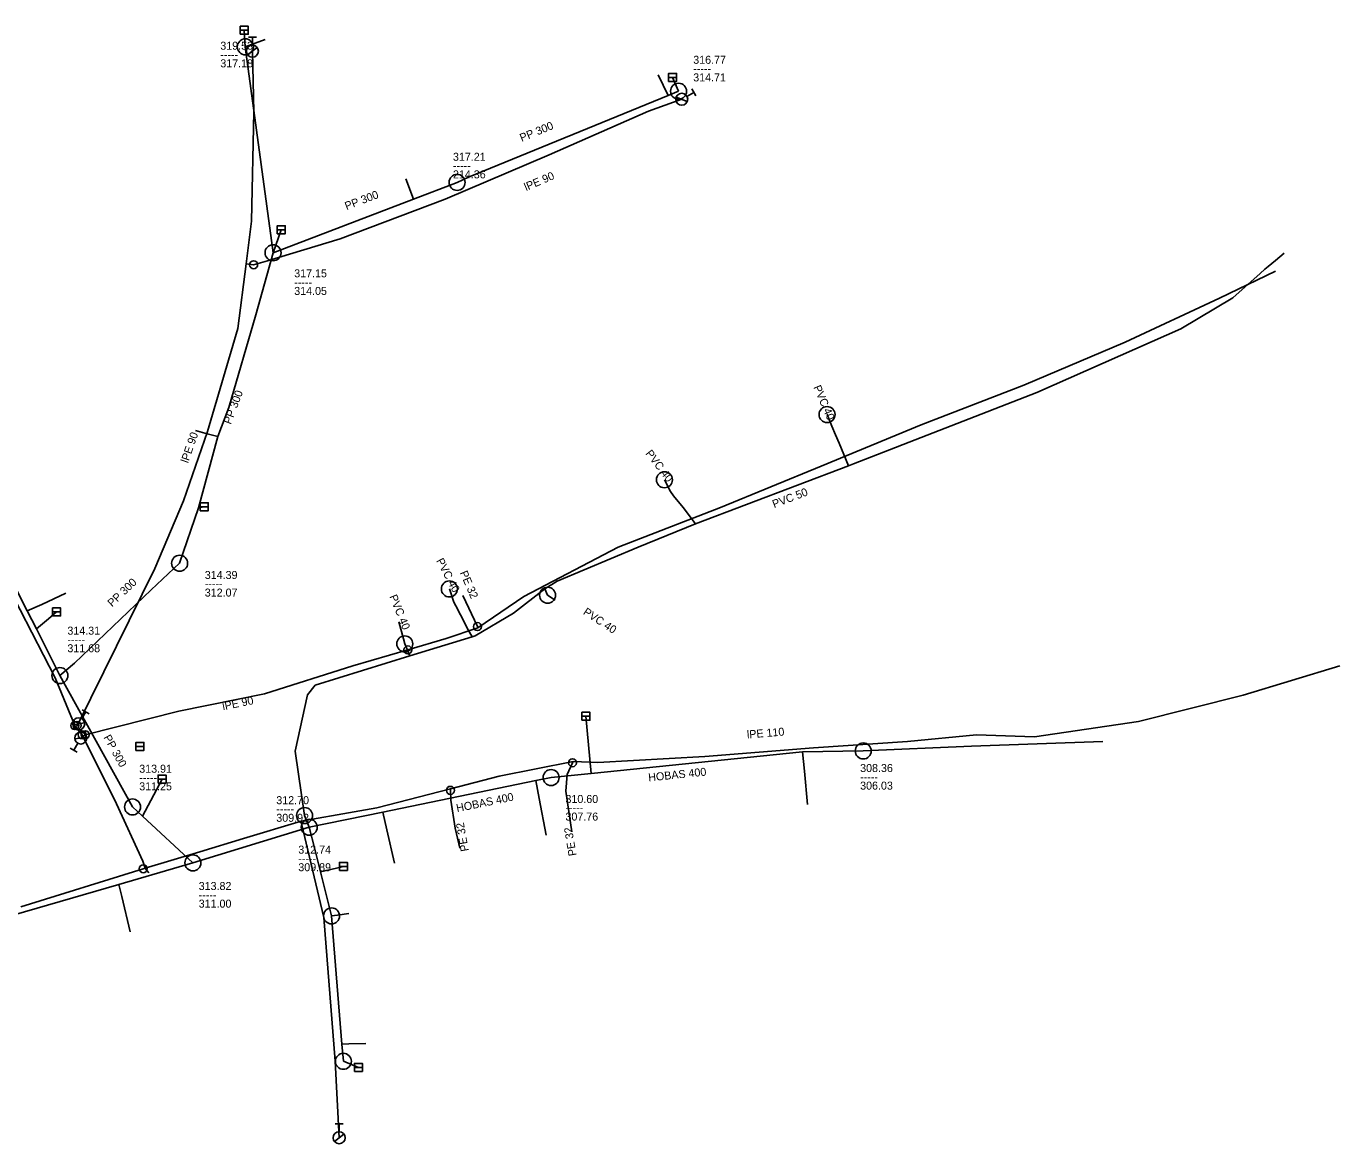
# Model space of a CAD drawing. Extents: x -770550 to -770198, y -1055065 to -1054790.
# Drawn here: x -770362.5 to -770198.4, y -1054983.3 to -1054843.6 of the extents above; entities that cross this region are included whole.
import ezdxf

# ---------------------------------------------------------------- set-up
doc = ezdxf.new("R2010")
doc.units = 0
doc.layers.add('Level 0', color=7, linetype='Continuous')

msp = doc.modelspace()

# ---------------------------------------------------------------- linework, layer by layer
at = {"layer": 'Level 0'}
for p, q in [((-770335.78, -1054844.13), (-770334.78, -1054844.13)), ((-770335.28, -1054844.13), (-770335.15, -1054846.2)), ((-770335.15, -1054846.2), (-770332.67, -1054845.28)), ((-770335.15, -1054846.2), (-770331.74, -1054871.32)), ((-770334.86, -1054847.2), (-770333.68, -1054846.28)), ((-770334.77, -1054844.99), (-770333.77, -1054844.99)), ((-770334.27, -1054845.99), (-770334.27, -1054844.99)), ((-770334.1, -1054854.32), (-770334.27, -1054846.74)), ((-770282.29, -1054852.28), (-770283.55, -1054849.69)), ((-770282.25, -1054850.03), (-770281.25, -1054850.03)), ((-770281.75, -1054850.03), (-770281, -1054851.75)), ((-770279.34, -1054851.45), (-770278.84, -1054852.32)), ((-770282.29, -1054852.28), (-770307.27, -1054862.47)), ((-770284.76, -1054854.22), (-770280.61, -1054852.76)), ((-770281, -1054851.75), (-770282.29, -1054852.28)), ((-770281.3, -1054852.48), (-770279.91, -1054853.04)), ((-770279.96, -1054852.39), (-770279.09, -1054851.89)), ((-770334.4, -1054867.97), (-770334.1, -1054854.32)), ((-770297.19, -1054859.7), (-770284.76, -1054854.22)), ((-770310.16, -1054865.24), (-770297.19, -1054859.7)), ((-770314.13, -1054865.26), (-770315.08, -1054862.68)), ((-770307.27, -1054862.47), (-770308.68, -1054863.14)), ((-770308.68, -1054863.14), (-770314.13, -1054865.26)), ((-770314.13, -1054865.26), (-770331.69, -1054871.94)), ((-770323.3, -1054870.19), (-770310.16, -1054865.24)), ((-770335.06, -1054873.31), (-770334.4, -1054867.97)), ((-770330.66, -1054869.06), (-770331.69, -1054871.94)), ((-770331.16, -1054869.06), (-770330.16, -1054869.06)), ((-770332.37, -1054872.94), (-770323.3, -1054870.19)), ((-770331.69, -1054871.94), (-770333.83, -1054879.69)), ((-770331.74, -1054871.32), (-770331.69, -1054871.94)), ((-770205.3, -1054871.97), (-770206.41, -1054872.9)), ((-770336.07, -1054881.39), (-770335.06, -1054873.31)), ((-770335.06, -1054873.31), (-770334.11, -1054873.43)), ((-770334.11, -1054873.43), (-770332.37, -1054872.94)), ((-770206.41, -1054874.22), (-770213.4, -1054877.62)), ((-770207.72, -1054873.99), (-770208.3, -1054874.51)), ((-770207.33, -1054873.67), (-770207.72, -1054873.99)), ((-770206.41, -1054872.9), (-770207.33, -1054873.67)), ((-770208.3, -1054874.51), (-770211.72, -1054877.57)), ((-770213.4, -1054877.62), (-770225.2, -1054883.12)), ((-770211.72, -1054877.57), (-770218.24, -1054881.44)), ((-770333.83, -1054879.69), (-770337.22, -1054891.29)), ((-770339.86, -1054894.27), (-770336.07, -1054881.39)), ((-770218.24, -1054881.44), (-770221.83, -1054883.03)), ((-770225.2, -1054883.12), (-770237.84, -1054888.47)), ((-770221.83, -1054883.03), (-770236.24, -1054889.42)), ((-770237.84, -1054888.47), (-770250.69, -1054893.44)), ((-770236.24, -1054889.42), (-770259.16, -1054898.34)), ((-770337.22, -1054891.29), (-770338.59, -1054894.92)), ((-770262.45, -1054892.16), (-770261.86, -1054893.62)), ((-770250.69, -1054893.44), (-770263.17, -1054898.6)), ((-770261.86, -1054893.62), (-770261.4, -1054894.69)), ((-770342.87, -1054902.96), (-770339.86, -1054894.27)), ((-770339.9, -1054894.56), (-770341.36, -1054894.17)), ((-770338.59, -1054894.92), (-770341.02, -1054903.82)), ((-770338.59, -1054894.92), (-770339.9, -1054894.56)), ((-770261.4, -1054894.69), (-770260.95, -1054895.74)), ((-770260.95, -1054895.74), (-770259.75, -1054898.56)), ((-770259.75, -1054898.56), (-770278.9, -1054905.84)), ((-770263.17, -1054898.6), (-770275.76, -1054903.79)), ((-770259.16, -1054898.34), (-770259.75, -1054898.56)), ((-770282.03, -1054901.79), (-770282.77, -1054900.31)), ((-770281.64, -1054902.3), (-770282.03, -1054901.79)), ((-770280.43, -1054903.79), (-770281.64, -1054902.3)), ((-770346.45, -1054911.4), (-770342.87, -1054902.96)), ((-770341.02, -1054903.82), (-770343.36, -1054910.75)), ((-770341.02, -1054903.82), (-770340.29, -1054903.68)), ((-770340.79, -1054903.68), (-770339.79, -1054903.68)), ((-770275.76, -1054903.79), (-770288.55, -1054908.73)), ((-770278.9, -1054905.84), (-770280.43, -1054903.79)), ((-770278.9, -1054905.84), (-770286.07, -1054908.72)), ((-770288.55, -1054908.73), (-770300.36, -1054914.91)), ((-770286.07, -1054908.72), (-770296.16, -1054912.97)), ((-770358.93, -1054925.08), (-770366.23, -1054910.92)), ((-770356.06, -1054930.8), (-770346.45, -1054911.4)), ((-770343.36, -1054910.75), (-770346.93, -1054914.07)), ((-770296.16, -1054912.97), (-770297.73, -1054913.94)), ((-770363.65, -1054914.24), (-770362.41, -1054916.7)), ((-770360.59, -1054915.89), (-770357.59, -1054914.5)), ((-770346.93, -1054914.07), (-770356.49, -1054923.23)), ((-770309.09, -1054915.61), (-770309.65, -1054913.96)), ((-770307.98, -1054914.76), (-770306.14, -1054918.66)), ((-770300.36, -1054914.91), (-770306.08, -1054918.8)), ((-770297.73, -1054913.94), (-770301.63, -1054916.99)), ((-770297.73, -1054913.94), (-770297.37, -1054914.74)), ((-770297.37, -1054914.74), (-770296.42, -1054915.37)), ((-770362.41, -1054916.7), (-770360.59, -1054915.89)), ((-770362.41, -1054916.7), (-770361.27, -1054918.95)), ((-770358.74, -1054916.83), (-770359.76, -1054917.69)), ((-770359.24, -1054916.83), (-770358.24, -1054916.83)), ((-770308.86, -1054916.08), (-770309.09, -1054915.61)), ((-770308.27, -1054917.19), (-770308.86, -1054916.08)), ((-770301.63, -1054916.99), (-770306.44, -1054919.81)), ((-770359.76, -1054917.69), (-770361.27, -1054918.95)), ((-770315.98, -1054918.08), (-770315.4, -1054920.19)), ((-770307.28, -1054919.07), (-770308.27, -1054917.19)), ((-770306.14, -1054918.66), (-770306.08, -1054918.8)), ((-770361.27, -1054918.95), (-770358.32, -1054924.78)), ((-770315.4, -1054920.19), (-770315.22, -1054920.82)), ((-770310.05, -1054920.17), (-770314.84, -1054921.57)), ((-770306.82, -1054919.93), (-770314.58, -1054922.33)), ((-770306.08, -1054918.8), (-770310.05, -1054920.17)), ((-770306.82, -1054919.93), (-770307.28, -1054919.07)), ((-770306.44, -1054919.81), (-770306.82, -1054919.93)), ((-770314.84, -1054921.57), (-770321.72, -1054923.58)), ((-770315.22, -1054920.82), (-770314.89, -1054921.63)), ((-770314.89, -1054921.63), (-770314.58, -1054922.33)), ((-770356.49, -1054923.23), (-770358.32, -1054924.78)), ((-770321.72, -1054923.58), (-770332.76, -1054927.06)), ((-770314.58, -1054922.33), (-770326.42, -1054926)), ((-770198.37, -1054923.56), (-770210.44, -1054927.22)), ((-770356.47, -1054931.04), (-770358.93, -1054925.08)), ((-770358.32, -1054924.78), (-770349.25, -1054941.21)), ((-770326.42, -1054926), (-770327.36, -1054927.2)), ((-770332.76, -1054927.06), (-770343.47, -1054929.24)), ((-770327.36, -1054927.2), (-770328.93, -1054934.25)), ((-770210.44, -1054927.22), (-770223.51, -1054930.54)), ((-770355.6, -1054930.17), (-770355.1, -1054929.3)), ((-770355.54, -1054929.05), (-770354.67, -1054929.55)), ((-770343.47, -1054929.24), (-770355.16, -1054932.19)), ((-770293.09, -1054929.87), (-770292.09, -1054929.87)), ((-770292.59, -1054929.87), (-770291.91, -1054937.02)), ((-770356.72, -1054930.93), (-770355.24, -1054930.71)), ((-770356.36, -1054931.18), (-770356.47, -1054931.04)), ((-770356.36, -1054931.18), (-770356.17, -1054931.02)), ((-770355.55, -1054932.18), (-770356.36, -1054931.18)), ((-770356.17, -1054931.02), (-770356.06, -1054930.8)), ((-770356.17, -1054931.02), (-770355.98, -1054930.82)), ((-770223.51, -1054930.54), (-770236.53, -1054932.46)), ((-770356.09, -1054933.24), (-770356.59, -1054934.11)), ((-770354.98, -1054932.48), (-770356.46, -1054932.7)), ((-770355.72, -1054932.59), (-770355.47, -1054932.35)), ((-770355.47, -1054932.35), (-770355.55, -1054932.18)), ((-770355.16, -1054932.19), (-770355.47, -1054932.35)), ((-770351.25, -1054940.82), (-770355.47, -1054932.35)), ((-770252.41, -1054933.02), (-770264.13, -1054933.81)), ((-770243.76, -1054932.2), (-770252.41, -1054933.02)), ((-770244.41, -1054933.59), (-770227.96, -1054933.02)), ((-770236.53, -1054932.46), (-770243.76, -1054932.2)), ((-770356.16, -1054934.36), (-770357.03, -1054933.86)), ((-770348.82, -1054933.63), (-770347.82, -1054933.63)), ((-770328.93, -1054934.25), (-770327.74, -1054942.28)), ((-770291.91, -1054937.02), (-770265.51, -1054934.33)), ((-770277.74, -1054934.9), (-770291.08, -1054935.63)), ((-770264.13, -1054933.81), (-770277.74, -1054934.9)), ((-770265.51, -1054934.33), (-770257.92, -1054934.21)), ((-770265.28, -1054936.74), (-770265.51, -1054934.33)), ((-770257.92, -1054934.21), (-770244.41, -1054933.59)), ((-770294.18, -1054935.51), (-770303.42, -1054937.34)), ((-770294.26, -1054935.69), (-770294.94, -1054937.13)), ((-770294.18, -1054935.51), (-770294.26, -1054935.69)), ((-770291.08, -1054935.63), (-770294.18, -1054935.51)), ((-770264.88, -1054940.89), (-770265.28, -1054936.74)), ((-770348.01, -1054942.36), (-770345.56, -1054937.73)), ((-770346.06, -1054937.73), (-770345.06, -1054937.73)), ((-770317.97, -1054941.85), (-770298.85, -1054937.92)), ((-770303.42, -1054937.34), (-770309.51, -1054938.93)), ((-770298.85, -1054937.92), (-770296.94, -1054937.53)), ((-770298.43, -1054940.13), (-770298.85, -1054937.92)), ((-770296.94, -1054937.53), (-770291.91, -1054937.02)), ((-770294.94, -1054937.13), (-770295.09, -1054939.25)), ((-770309.51, -1054938.93), (-770318.71, -1054941.33)), ((-770309.51, -1054939.13), (-770309.51, -1054938.93)), ((-770309.45, -1054940.35), (-770309.51, -1054939.13)), ((-770295.09, -1054939.25), (-770294.34, -1054944.32)), ((-770347.98, -1054948), (-770351.25, -1054940.82)), ((-770349.25, -1054941.21), (-770348.01, -1054942.36)), ((-770318.71, -1054941.33), (-770321.56, -1054941.83)), ((-770308.92, -1054943.87), (-770309.45, -1054940.35)), ((-770297.55, -1054944.75), (-770298.43, -1054940.13)), ((-770348.01, -1054942.36), (-770341.7, -1054948.2)), ((-770328.19, -1054942.99), (-770335.37, -1054945.17)), ((-770321.56, -1054941.83), (-770328.19, -1054942.99)), ((-770328.19, -1054942.99), (-770328.12, -1054943.28)), ((-770328.12, -1054943.28), (-770325.33, -1054955.02)), ((-770327.74, -1054942.28), (-770327.16, -1054943.74)), ((-770327.16, -1054943.74), (-770317.97, -1054941.85)), ((-770317.97, -1054941.85), (-770317.46, -1054944.05)), ((-770341.7, -1054948.2), (-770327.16, -1054943.74)), ((-770326.47, -1054946.48), (-770327.16, -1054943.74)), ((-770317.46, -1054944.05), (-770316.5, -1054948.24)), ((-770308.35, -1054946.36), (-770308.92, -1054943.87)), ((-770335.37, -1054945.17), (-770340.85, -1054946.81)), ((-770325.76, -1054949.31), (-770326.47, -1054946.48)), ((-770350.96, -1054950.9), (-770341.7, -1054948.2)), ((-770347.82, -1054948.37), (-770347.98, -1054948)), ((-770340.85, -1054946.81), (-770347.67, -1054948.86)), ((-770347.91, -1054948.93), (-770363.2, -1054953.68)), ((-770347.67, -1054948.86), (-770347.91, -1054948.93)), ((-770347.67, -1054948.86), (-770347.82, -1054948.37)), ((-770347.42, -1054949.17), (-770347.67, -1054948.86)), ((-770347.21, -1054949.42), (-770347.42, -1054949.17)), ((-770324.47, -1054949.01), (-770325.76, -1054949.31)), ((-770324.37, -1054954.83), (-770325.76, -1054949.31)), ((-770322.9, -1054948.64), (-770324.47, -1054949.01)), ((-770323.4, -1054948.64), (-770322.4, -1054948.64)), ((-770365.61, -1054955.16), (-770350.96, -1054950.9)), ((-770350.6, -1054952.4), (-770350.96, -1054950.9)), ((-770349.55, -1054956.83), (-770350.6, -1054952.4)), ((-770323.62, -1054954.72), (-770324.37, -1054954.83)), ((-770323.07, -1054970.86), (-770324.37, -1054954.83)), ((-770322.21, -1054954.52), (-770323.62, -1054954.72)), ((-770325.33, -1054955.02), (-770323.91, -1054972.96)), ((-770323.07, -1054970.86), (-770322.23, -1054970.83)), ((-770322.9, -1054973), (-770323.07, -1054970.86)), ((-770322.23, -1054970.83), (-770320.07, -1054970.77)), ((-770323.91, -1054972.96), (-770323.42, -1054982.55)), ((-770322.9, -1054973), (-770321.01, -1054973.77)), ((-770321.51, -1054973.77), (-770320.51, -1054973.77)), ((-770323.92, -1054980.8), (-770322.92, -1054980.8)), ((-770323.42, -1054981.8), (-770323.42, -1054980.8)), ((-770324.01, -1054983.01), (-770322.83, -1054982.09))]:
    msp.add_line(p, q, dxfattribs=at)
for points in [[(-770335.78, -1054844.63), (-770334.78, -1054844.63), (-770334.78, -1054843.63), (-770335.78, -1054843.63)], [(-770282.25, -1054850.53), (-770281.25, -1054850.53), (-770281.25, -1054849.53), (-770282.25, -1054849.53)], [(-770331.16, -1054869.56), (-770330.16, -1054869.56), (-770330.16, -1054868.56), (-770331.16, -1054868.56)], [(-770340.79, -1054904.18), (-770339.79, -1054904.18), (-770339.79, -1054903.18), (-770340.79, -1054903.18)], [(-770359.24, -1054917.33), (-770358.24, -1054917.33), (-770358.24, -1054916.33), (-770359.24, -1054916.33)], [(-770293.09, -1054930.37), (-770292.09, -1054930.37), (-770292.09, -1054929.37), (-770293.09, -1054929.37)], [(-770348.82, -1054934.13), (-770347.82, -1054934.13), (-770347.82, -1054933.13), (-770348.82, -1054933.13)], [(-770346.06, -1054938.23), (-770345.06, -1054938.23), (-770345.06, -1054937.23), (-770346.06, -1054937.23)], [(-770323.4, -1054949.14), (-770322.4, -1054949.14), (-770322.4, -1054948.14), (-770323.4, -1054948.14)], [(-770321.51, -1054974.27), (-770320.51, -1054974.27), (-770320.51, -1054973.27), (-770321.51, -1054973.27)]]:
    msp.add_lwpolyline(points, close=True, dxfattribs=at)
for centre, radius in [((-770335.15, -1054846.2), 1), ((-770334.27, -1054846.74), 0.75), ((-770281, -1054851.75), 1), ((-770280.61, -1054852.76), 0.75), ((-770308.68, -1054863.14), 1), ((-770331.69, -1054871.94), 1), ((-770334.11, -1054873.43), 0.5), ((-770262.45, -1054892.16), 1), ((-770282.77, -1054900.31), 1), ((-770343.36, -1054910.75), 1), ((-770309.65, -1054913.96), 1), ((-770297.37, -1054914.74), 1), ((-770306.14, -1054918.66), 0.5), ((-770315.22, -1054920.82), 1), ((-770314.84, -1054921.57), 0.5), ((-770358.32, -1054924.78), 1), ((-770355.98, -1054930.82), 0.75), ((-770356.47, -1054931.04), 0.5), ((-770356.17, -1054931.02), 0.5), ((-770355.72, -1054932.59), 0.75), ((-770355.55, -1054932.18), 0.5), ((-770355.16, -1054932.19), 0.5), ((-770257.92, -1054934.21), 1), ((-770296.94, -1054937.53), 1), ((-770294.26, -1054935.69), 0.5), ((-770309.51, -1054939.13), 0.5), ((-770349.25, -1054941.21), 1), ((-770327.74, -1054942.28), 1), ((-770327.16, -1054943.74), 1), ((-770341.7, -1054948.2), 1), ((-770347.91, -1054948.93), 0.5), ((-770324.37, -1054954.83), 1), ((-770322.9, -1054973), 1), ((-770323.42, -1054982.55), 0.75)]:
    msp.add_circle(centre, radius, dxfattribs=at)

# ---------------------------------------------------------------- texts
for s, p in [('319.53', (-770338.28, -1054846.56)), ('317.18', (-770338.28, -1054848.76)), ('-----', (-770338.28, -1054847.66)), ('316.77', (-770279.17, -1054848.32)), ('314.71', (-770279.17, -1054850.52)), ('-----', (-770279.17, -1054849.42)), ('317.21', (-770309.2, -1054860.44)), ('-----', (-770309.2, -1054861.54)), ('214.36', (-770309.2, -1054862.64)), ('317.15', (-770329.04, -1054875.01)), ('-----', (-770329.04, -1054876.11)), ('314.05', (-770329.04, -1054877.21)), ('314.39', (-770340.22, -1054912.71)), ('-----', (-770340.22, -1054913.81)), ('312.07', (-770340.22, -1054914.91)), ('314.31', (-770357.39, -1054919.67)), ('-----', (-770357.39, -1054920.77)), ('311.68', (-770357.39, -1054921.87)), ('313.91', (-770348.41, -1054936.93)), ('308.36', (-770258.31, -1054936.84)), ('311.25', (-770348.41, -1054939.13)), ('-----', (-770348.41, -1054938.03)), ('306.03', (-770258.31, -1054939.04)), ('-----', (-770258.31, -1054937.94)), ('312.70', (-770331.28, -1054940.86)), ('310.60', (-770295.14, -1054940.71)), ('-----', (-770331.28, -1054941.96)), ('-----', (-770295.14, -1054941.81)), ('309.92', (-770331.28, -1054943.06)), ('307.76', (-770295.14, -1054942.91)), ('312.74', (-770328.53, -1054947.04)), ('309.89', (-770328.53, -1054949.24)), ('-----', (-770328.53, -1054948.14)), ('313.82', (-770340.98, -1054951.59)), ('311.00', (-770340.98, -1054953.79)), ('-----', (-770340.98, -1054952.69))]:
    msp.add_text(s, height=1, dxfattribs=at).set_placement(p)
for s, rotation, p in [('PP 300', 22.192, (-770300.61, -1054858.08)), ('lPE 90', 23.129, (-770300.05, -1054864.23)), ('PP 300', 20.827, (-770322.5, -1054866.61)), ('PP 300', 69.323, (-770336.97, -1054893.46)), ('PVC 40', 293.199, (-770264.18, -1054888.74)), ('lPE 90', 70.895, (-770342.31, -1054898.29)), ('PVC 40', 307.405, (-770285.19, -1054897.04)), ('PVC 50', 20.815, (-770269.06, -1054903.86)), ('PVC 40', 297.992, (-770311.33, -1054910.43)), ('PE 32', 293.199, (-770308.36, -1054911.93)), ('PP 300', 43.776, (-770351.8, -1054916.27)), ('PVC 40', 292.166, (-770317.17, -1054914.9)), ('PVC 40', 326.449, (-770293.02, -1054917.06)), ('lPE 90', 11.505, (-770337.92, -1054929.13)), ('lPE 110', 4.579, (-770272.42, -1054932.65)), ('PP 300', 298.9, (-770352.91, -1054932.51)), ('HOBAS 400', 5.818, (-770284.74, -1054938.02)), ('HOBAS 400', 11.615, (-770308.68, -1054941.86)), ('PE 32', 100, (-770307.22, -1054946.68)), ('PE 32', 99.616, (-770293.74, -1054947.25))]:
    msp.add_text(s, height=1, rotation=rotation, dxfattribs=at).set_placement(p)

doc.saveas('drawing.dxf')
